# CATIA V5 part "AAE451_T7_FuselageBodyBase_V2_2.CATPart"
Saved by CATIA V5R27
Part number: Part7
Bounding box of the stored display mesh (mm): x -98.431 to 98.431, y -100 to 100, z -59.999 to 0
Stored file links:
  W:\AAE 451\AAE451_T7_FuselageAssemble_V2\AAE451_T7_FuselageAssemble_V2\AAE451_T7_FuselageBodyBase_V2_2.CATPart
  W:\AAE 451\AAE451_T7_FuselageBody.CATPart
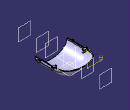
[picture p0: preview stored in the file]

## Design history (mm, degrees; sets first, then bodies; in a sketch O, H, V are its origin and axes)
Body1 (main body)
Body2
  Plane1: type Offset, RefPlane zx-plane, Offset 250, reversed
  Plane2: type Offset, RefPlane zx-plane, Offset 100
  Sketch1 on Plane1, origin (0, -250, 0), H (-1, 0, 0), V (0, 0, 1)
    circle A1 centre (0, 0) radius 24.5
    distance O A1 = 24.5
  Plane3: type Offset, RefPlane zx-plane, Offset 150, reversed
  Sketch2 on Plane2, origin (0, 100, 0), H (-1, 0, 0), V (0, 0, 1)
    construction line L1 (0, 60) -> (0, -40)
    point P1 (0, 60)
    construction line L2 (-92.2886, 30) -> (87.7114, 30)
    point P5 (0, 30)
    coincidence: P1 V, P5 L2, P5 L1
    vertical: L1 V
    horizontal: L2 H
  Sketch3 on Plane2, origin (0, 100, 0), H (-1, 0, 0), V (0, 0, 1)
    construction line L1 (0, -100) -> (0, 70)
    point P1 (0, -100)
    construction line L2 (-103.4986, 30) -> (116.5014, 30)
    point P5 (0, 30)
    point P6 (0, 60)
    construction line L3 (-60, 60) -> (60, 60)
    point P7 (-60, 60)
    reference projected curve E1 from Sketch4.E1
    ellipse A1 centre (0, 60) semi-axes 60, 35 rotation 180 from (-60, 60) to (60, 60)
    point P8 (-60, 60)
    point P9 (60, 60)
    point P10 (60, 60)
    point P11 (-60, 60)
    ellipse A2 centre (0, 60) semi-axes 60, 35 rotation 180 from (-60, 60) to (60, 60)
    "Radius" A1 = 60
    "Radius" A1 = 35
    coincidence: P1 V, P5 L2, P5 L1, P6 L1, A1 P7, P7 L3, P6 L3
    vertical: L1 V
    horizontal: L2 H, L3 H, A1 H
    tangency: L3 E1
    symmetry: P9 P10 L3, P8 P11 L3, A1 A2 L3
  Sketch4 on zx-plane, origin (0, 0, 0), H (-1, 0, 0), V (0, 0, 1)
    projected curve E1 from Sketch5.A1
  Sketch5 on Plane3, origin (0, -150, 0), H (-1, 0, 0), V (0, 0, 1)
    construction line L1 (50, 50) -> (50, -50)
    construction line L2 (50, -50) -> (-50, -50)
    construction line L3 (-50, -50) -> (-50, 50)
    construction line L4 (-50, 50) -> (50, 50)
    point P1 (50, 50)
    point P2 (50, -50)
    point P3 (-50, -50)
    point P4 (-50, 50)
    construction line L5 (0, -60) -> (0, 90)
    point P5 (0, -60)
    construction line L6 (-100, 0) -> (110, 0)
    point P7 (-100, 0)
    ellipse A1 centre (0, 0) semi-axes 90.4534, 60 rotation 0
    point P9 (0, 60)
    length L1 = 100
    length L4 = 100
    vertical: L1 V, L3 V, L5 V
    horizontal: L2 H, L4 H, L6 H, A1 H
    equidistance: L1 L3 O, L2 L4 O
    coincidence: P5 V, P7 H, P9 L5, A1 P9, P2 A1, A1 P3, P1 A1, P4 A1
    parallelism: A1 L6
  Loft1: solid, Sections (Sketch3; Sketch4; Sketch5; Sketch1)
  Sketch6 on face of Loft1, origin (0, 100, 0), H (-1, 0, 0), V (0, 0, 1)
    line L1 (-70, 95) -> (70, 95)
    line L2 (70, 95) -> (70, 60)
    line L3 (70, 60) -> (-70, 60)
    line L4 (-70, 60) -> (-70, 95)
    reference projected curve E1 from edge [face of Loft1 | face of Loft1]
    construction line L5 (-60, 60) -> (60, 60)
    length L1 = 140
    horizontal: L1 H, L3 H, L5 H
    vertical: L2 V, L4 V
    coincidence: L3 L5
    tangency: L1 E1
    symmetry: L4 L2 V
  Pocket1: profile Sketch6, direction (0, -1, 0), through (limit type 6)
  Plane4: type Offset, RefPlane Plane2, Offset 100
  Sketch7 on Plane4, origin (0, 200, 0), H (-1, 0, 0), V (0, 0, 1)
    projected line E2 (-60, 60) -> (60, 60) from edge [face of Loft1 | face of Pocket1 from Sketch6.L3]
  Pad1: profile Sketch7, direction (0, 1, 0), up to the existing solid (limit type 3)
  Sketch8 on face of Loft1, origin (0, -250, 0), H (1, 0, 0), V (0, 0, 1)
    line L1 (-97.5192, 0) -> (97.5192, 0)
    point P1 (-97.5192, 0)
    point P2 (97.5192, 0)
    projected line E1 (-62.8781, 60) -> (63.056, 60) from edge [face of Loft1 | face of Pad1]
    line L2 (-97.5192, 0) -> (-62.8781, 60)
    line L3 (97.5192, 0) -> (63.056, 60)
    angle L1 L2 = 60
    horizontal: L1 H
    symmetry: P1 P2 V
    coincidence: H L1
  Pocket2: profile Sketch8, direction (0, 1, 0), through (limit type 3)
  Shell1: ExtOffset 0, Face face of Pocket2 from Sketch8.L1, IntOffset 4
  Sketch9 on face of Pocket2 from Sketch8.L1, origin (0, 0, 0), H (1, 0, 0), V (0, 1, 0)
    arc A1 centre (93.4412, -150) radius 5 from (93.4412, -155) to (93.4412, -145) ccw
    point P1 (93.4412, -150)
    line L1 (93.4412, -145) -> (86.453, -145)
    point P2 (86.453, -145)
    line L2 (93.4412, -155) -> (86.4293, -155)
    point P3 (86.4293, -155)
    reference projected curve E1 from edge [face of Pocket2 from Sketch8.L1 | face of Shell1]
    reference projected curve E2 from edge [face of Shell1 | face of Pocket2 from Sketch8.L1]
    reference intersected line E3 through (0, -150) direction (-1, 0) from Plane3
    line L3 (86.453, -145) -> (86.4293, -155)
    distance L1 L2 = 10
    distance L3 P1 = 7
    horizontal: L1 H, L2 H
    tangency: L1 A1, L2 A1
    coincidence: P3 E1, P2 E2, E3 P1
  Pad2: profile Sketch9, direction (0, 0, -1), length 10
  RectPattern1: of Pad2, direction 1 instances 3, spacing 75, along yz-plane
  Mirror1: of RectPattern1, about yz-plane
  Plane5: type Offset, RefPlane xy-plane, Offset 55, reversed
  Sketch10 on Plane5, origin (0, 0, -55), H (1, 0, 0), V (0, 1, 0)
    line L1 (67.5, -137.75) -> (-67.5, -137.75)
    line L2 (-67.5, -137.75) -> (-67.5, -162.25)
    line L3 (-67.5, -162.25) -> (67.5, -162.25)
    line L4 (67.5, -162.25) -> (67.5, -137.75)
    construction line L5 (132.2933, -150) -> (-145.9619, -150)
    distance L4 L2 = 135
    length L2 = 24.5
    distance L5 H = 150
    horizontal: L1 H, L3 H
    vertical: L2 V, L4 V
    symmetry: L4 L2 V, L1 L3 L5
  Pad3: profile Sketch10, direction (0, 0, -1), length 12, opposite side up to the existing solid (limit type 2)
  Fillet1: radius 10, on edge [end face of Pad3 | face of Pad3 from Sketch10.L4]; edge [end face of Pad3 | face of Pad3 from Sketch10.L2]
  Sketch11 on face of RectPattern1, origin (0, 0, 0), H (1, 0, 0), V (0, 1, 0)
    circle A1 centre (93.4412, -150) radius 2.5
    reference projected arc E1 centre (93.4412, -150) radius 5 from (93.4412, -155) to (93.4412, -145) ccw from edge [face of Pad2 from Sketch9.A1 | face of RectPattern1]
    radius A1 = 2.5
    concentricity: A1 E1
  Pocket3: profile Sketch11, direction (0, 0, -1), through (limit type 3)
  RectPattern2: of Pocket3, direction 1 instances 3, spacing 75, along yz-plane
  Mirror2: of RectPattern2, about yz-plane
  Plane6 "PRINT CAPACITY": type Offset, RefPlane Plane1, Offset 150
  Sketch12 on Plane6, origin (0, -100, 0), H (-1, 0, 0), V (0, 0, 1)
    point P1 (-3.2182, -33.5)
    line L1 (124.5912, 0) -> (124.5912, -67)
    line L2 (124.5912, -67) -> (-131.0276, -67)
    line L3 (-131.0276, -67) -> (-131.0276, 0)
    line L4 (-131.0276, 0) -> (124.5912, 0)
    reference projected line E1 (-67.5, -67) -> (67.5, -67) from edge [end face of Pad3 | face of Pad3 from Sketch10.L1]
    vertical: L1 V, L3 V
    horizontal: L2 H, L4 H
    equidistance: L1 L3 P1, L2 L4 P1
    coincidence: L4 H, L2 E1
  Pocket4: profile Sketch12, direction (0, -1, 0), through (limit type 3)
  Sketch13 on face of RectPattern1, origin (0, 0, 0), H (1, 0, 0), V (0, 1, 0)
    arc A1 centre (76.4411, 0) radius 5 from (76.4411, 5) to (76.4411, -5) ccw
    point P1 (76.4411, 0)
    line L1 (76.4411, -5) -> (86.4293, -5)
    point P2 (86.4293, -5)
    line L2 (86.453, 5) -> (76.4411, 5)
    point P3 (86.453, 5)
    reference projected line E1 (86.4495, 3.5087) -> (86.4293, -5) from edge [face of RectPattern1 | face of RectPattern1]
    reference projected line E2 (86.4495, 3.5087) -> (86.4293, -5) from edge [face of RectPattern1 | face of RectPattern1]
    line L3 (86.4293, -5) -> (86.453, 5)
    construction line L4 (93.4412, 0) -> (76.4411, 0)
    point P4 (93.4412, 0)
    reference projected circle E3 centre (93.4412, 0) radius 2.5 from edge [face of RectPattern1 | face of RectPattern2]
    radius A1 = 5
    distance P1 L3 = 10
    coincidence: P3 E1, P2 E2
    horizontal: L2 H, L1 H, L4 H
    tangency: L2 A1, L1 A1
    concentricity: P4 E3
  Pad4: profile Sketch13, direction (0, 0, -1), length 13
  Sketch14 on face of Pad4, origin (77.0167, -0.3514, 0), H (1, 0, 0), V (0, 1, 0)
    point P1 (-0.5755, 0.3514)
    reference projected arc E1 centre (-0.5755, 0.3514) radius 5 from (-0.5755, 5.3514) to (-0.5755, -4.6486) ccw from edge [face of Pad4 from Sketch13.A1 | start face of Pad4]
    concentricity: P1 E1
  Hole1: placed by Sketch14, at (76.4411, 0, 0) direction (0, 0, -1), diameter 4.5, through (limit type 6), countersink depth 7.9, countersink angle 8
  Mirror3: of Pad4, Hole1, about yz-plane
